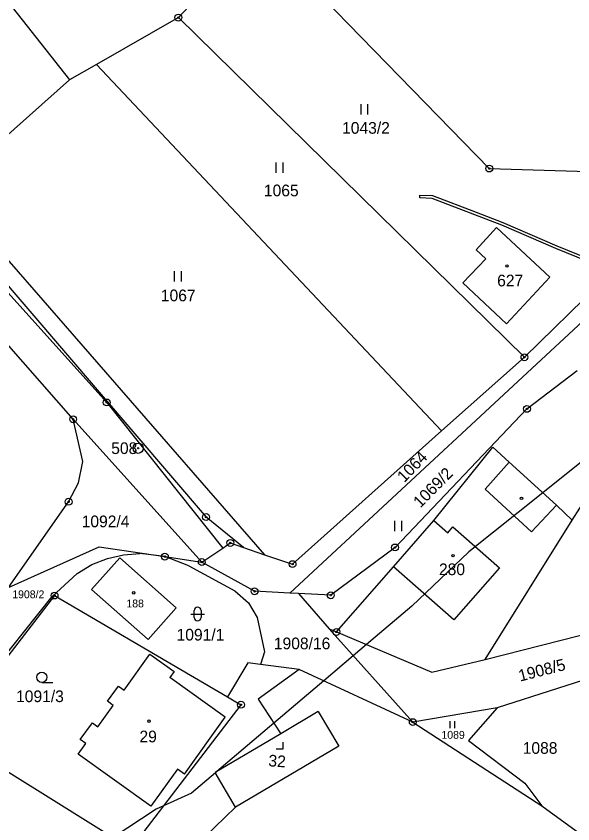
# Model space of a CAD drawing. Extents: x -445050 to -440454, y -1134563 to -1129741.
# Drawn here: x -440973 to -440892, y -1131697.7 to -1131580.2 of the extents above; entities that cross this region are included whole.
import ezdxf

# ---------------------------------------------------------------- set-up
doc = ezdxf.new("R2010")
doc.units = 0
for name, color, linetype in [('Vrstva 1', 7, 'Continuous'), ('Vrstva 16', 7, 'Continuous'), ('Vrstva 17', 7, 'Continuous'), ('Vrstva 18', 7, 'Continuous'), ('Vrstva 19', 7, 'Continuous'), ('Vrstva 24', 7, 'Continuous'), ('Vrstva 25', 7, 'Continuous'), ('Vrstva 3', 7, 'Continuous'), ('Vrstva 30', 7, 'Continuous'), ('Vrstva 37', 7, 'Continuous'), ('Vrstva 4', 7, 'Continuous'), ('Vrstva 52', 7, 'Continuous'), ('Vrstva 6', 7, 'Continuous')]:
    doc.layers.add(name, color=color, linetype=linetype)

msp = doc.modelspace()

# ---------------------------------------------------------------- linework, layer by layer
at = {"layer": 'Vrstva 1'}
for p, q in [((-440960.93, -1131657.44), (-440951.34, -1131658.85)), ((-440959.67, -1131659.1), (-440957.37, -1131658.57)), ((-440957.37, -1131658.57), (-440955.01, -1131658.4)), ((-440951.34, -1131658.85), (-440955.01, -1131658.4)), ((-440947.86, -1131660.19), (-440951.34, -1131658.85)), ((-440951.34, -1131658.85), (-440945.97, -1131659.64)), ((-440964.12, -1131661.32), (-440961.97, -1131660)), ((-440961.97, -1131660), (-440959.67, -1131659.1)), ((-440967.74, -1131664.66), (-440964.12, -1131661.32)), ((-440947.86, -1131660.19), (-440941.17, -1131663.84)), ((-440977.9, -1131677.35), (-440967.74, -1131664.66)), ((-440941.17, -1131663.84), (-440939.19, -1131665.55)), ((-440939.19, -1131665.55), (-440937.91, -1131667.71)), ((-440937.91, -1131667.71), (-440936.86, -1131672.68)), ((-440936.86, -1131672.68), (-440937.44, -1131674.52)), ((-440937.44, -1131674.52), (-440939.27, -1131674.27)), ((-440931.78, -1131675.28), (-440937.44, -1131674.52))]:
    msp.add_line(p, q, dxfattribs=at)
for points in [[(-441028.42, -1131556.07), (-440945.35, -1131653.09)], [(-440949.38, -1131580.44), (-440937.66, -1131567.98)], [(-440937.66, -1131567.98), (-440904.13, -1131602.39)], [(-440949.38, -1131580.44), (-440899.01, -1131629.84)], [(-440964.69, -1131638.87), (-441013.94, -1131582.78)], [(-440904.13, -1131602.39), (-440875.32, -1131603.26)], [(-440983.15, -1131605.46), (-440936.83, -1131658.56)], [(-440982.49, -1131611.24), (-440959.81, -1131636.42)], [(-440906.05, -1131614.2), (-440903.07, -1131610.99)], [(-440895.33, -1131618.19), (-440903.07, -1131610.99)], [(-440904.64, -1131615.52), (-440906.05, -1131614.2)], [(-440908, -1131619.04), (-440904.64, -1131615.52)], [(-440895.33, -1131618.19), (-440901.61, -1131624.99)], [(-440901.61, -1131624.99), (-440908, -1131619.04)], [(-440899.01, -1131629.84), (-440888.16, -1131619.27)], [(-440886.46, -1131620.79), (-440933.17, -1131664.15)], [(-440911.09, -1131640.57), (-440899.01, -1131629.84)], [(-440898.64, -1131637.35), (-440891.35, -1131631.79)], [(-440959.81, -1131636.42), (-440942.93, -1131657.6)], [(-440898.64, -1131637.35), (-440917.85, -1131657.51)], [(-440963.27, -1131645.03), (-440964.69, -1131638.87)], [(-440945.97, -1131659.64), (-440964.69, -1131638.87)], [(-440932.76, -1131659.94), (-440911.09, -1131640.57)], [(-440912.18, -1131653.61), (-440903.62, -1131642.93)], [(-440903.62, -1131642.93), (-440901.21, -1131645.12)], [(-440963.92, -1131648.09), (-440963.27, -1131645.03)], [(-440901.21, -1131645.12), (-440894.36, -1131651.34)], [(-440965.35, -1131650.86), (-440963.92, -1131648.09)], [(-440892.08, -1131653.56), (-440889.85, -1131650.07)], [(-440974.1, -1131663.33), (-440965.35, -1131650.86)], [(-440894.36, -1131651.34), (-440892.08, -1131653.56)], [(-440939.91, -1131657.51), (-440945.35, -1131653.09)], [(-440918.06, -1131660.32), (-440912.18, -1131653.61)], [(-440904.72, -1131673.81), (-440892.08, -1131653.56)], [(-440974.1, -1131663.33), (-440960.93, -1131657.44)], [(-440945.97, -1131659.64), (-440942.93, -1131657.6)], [(-440942.93, -1131657.6), (-440941.82, -1131656.86)], [(-440941.82, -1131656.86), (-440939.91, -1131657.51)], [(-440939.91, -1131657.51), (-440936.83, -1131658.56)], [(-440917.85, -1131657.51), (-440927.19, -1131664.47)], [(-440936.83, -1131658.56), (-440932.76, -1131659.94)], [(-440957.9, -1131659.04), (-440962.01, -1131663.64)], [(-440949.71, -1131666.28), (-440957.9, -1131659.04)], [(-440938.29, -1131663.89), (-440945.97, -1131659.64)], [(-440926.37, -1131669.8), (-440918.06, -1131660.32)], [(-440953.79, -1131670.9), (-440962.01, -1131663.64)], [(-440967.4, -1131664.5), (-440983, -1131684.66)], [(-440967.4, -1131664.5), (-440942.22, -1131679.25)], [(-440933.17, -1131664.15), (-440938.29, -1131663.89)], [(-440931.9, -1131664.22), (-440933.17, -1131664.15)], [(-440931.9, -1131664.22), (-440927.44, -1131669.35)], [(-440927.19, -1131664.47), (-440931.9, -1131664.22)], [(-440949.71, -1131666.28), (-440953.79, -1131670.9)], [(-440904.72, -1131673.81), (-440882.8, -1131668.24)], [(-440927.44, -1131669.35), (-440915.26, -1131682.92)], [(-440927.44, -1131669.35), (-440926.37, -1131669.8)], [(-440926.37, -1131669.8), (-440912.48, -1131675.65)], [(-440957.27, -1131678.27), (-440953.52, -1131673.03)], [(-440953.52, -1131673.03), (-440950, -1131675.55)], [(-440912.48, -1131675.65), (-440904.72, -1131673.81)], [(-440939.27, -1131674.27), (-440942.22, -1131679.25)], [(-440931.78, -1131675.28), (-440937.76, -1131679.59)], [(-440915.26, -1131682.92), (-440931.78, -1131675.28)], [(-440885.43, -1131675.22), (-440902.96, -1131680.85)], [(-440950, -1131675.55), (-440950.62, -1131676.41)], [(-440942.55, -1131682.18), (-440950.62, -1131676.41)], [(-440959.67, -1131679.89), (-440958.09, -1131677.68)], [(-440958.09, -1131677.68), (-440957.27, -1131678.27)], [(-440958.85, -1131680.48), (-440959.67, -1131679.89)], [(-440942.22, -1131679.25), (-440940.27, -1131680.39)], [(-440937.76, -1131679.59), (-440934.48, -1131684.6)], [(-440961.08, -1131683.59), (-440958.85, -1131680.48)], [(-440940.27, -1131680.39), (-440956.28, -1131701.3)], [(-440902.96, -1131680.85), (-440915.26, -1131682.92)], [(-440902.96, -1131680.85), (-440907.14, -1131685.6)], [(-440948.5, -1131690.49), (-440942.55, -1131682.18)], [(-440929.01, -1131681.38), (-440934.48, -1131684.6)], [(-440929.01, -1131681.38), (-440926.04, -1131686.41)], [(-440963.66, -1131685.46), (-440961.9, -1131683)], [(-440961.9, -1131683), (-440961.08, -1131683.59)], [(-440915.26, -1131682.92), (-440896.48, -1131695.1)], [(-440983, -1131684.66), (-440958.64, -1131699.84)], [(-440934.48, -1131684.6), (-440944.02, -1131690.24)], [(-440962.84, -1131686.04), (-440963.66, -1131685.46)], [(-440907.14, -1131685.6), (-440898.95, -1131691.78)], [(-440963.95, -1131687.6), (-440962.84, -1131686.04)], [(-440926.04, -1131686.41), (-440941.05, -1131695.27)], [(-440953.39, -1131695.16), (-440963.95, -1131687.6)], [(-440949.52, -1131689.76), (-440953.39, -1131695.16)], [(-440948.5, -1131690.49), (-440949.52, -1131689.76)], [(-440941.05, -1131695.27), (-440944.02, -1131690.24)], [(-440898.95, -1131691.78), (-440896.48, -1131695.1)], [(-440945.57, -1131699.63), (-440941.05, -1131695.27)], [(-440896.48, -1131695.1), (-440884.56, -1131703.79)]]:
    msp.add_lwpolyline(points, dxfattribs=at)
at = {"layer": 'Vrstva 24'}
for centre, radius in [((-440949.38, -1131580.44), 0.5), ((-440949.38, -1131580.44), 0.1), ((-440904.13, -1131602.39), 0.5), ((-440904.13, -1131602.39), 0.1), ((-440899.01, -1131629.84), 0.5), ((-440899.01, -1131629.84), 0.1), ((-440959.81, -1131636.42), 0.5), ((-440959.81, -1131636.42), 0.1), ((-440898.64, -1131637.35), 0.5), ((-440898.64, -1131637.35), 0.1), ((-440964.69, -1131638.87), 0.5), ((-440964.69, -1131638.87), 0.1), ((-440955.23, -1131643.07), 0.75), ((-440955.23, -1131643.07), 0.1), ((-440965.35, -1131650.86), 0.5), ((-440965.35, -1131650.86), 0.1), ((-440945.35, -1131653.09), 0.5), ((-440945.35, -1131653.09), 0.1), ((-440941.82, -1131656.86), 0.5), ((-440941.82, -1131656.86), 0.1), ((-440917.85, -1131657.51), 0.5), ((-440917.85, -1131657.51), 0.1), ((-440951.34, -1131658.85), 0.5), ((-440951.34, -1131658.85), 0.1), ((-440945.97, -1131659.64), 0.5), ((-440945.97, -1131659.64), 0.1), ((-440932.76, -1131659.94), 0.5), ((-440932.76, -1131659.94), 0.1), ((-440938.29, -1131663.89), 0.5), ((-440967.4, -1131664.5), 0.5), ((-440967.4, -1131664.5), 0.1), ((-440938.29, -1131663.89), 0.1), ((-440927.19, -1131664.47), 0.5), ((-440927.19, -1131664.47), 0.1), ((-440926.37, -1131669.8), 0.5), ((-440926.37, -1131669.8), 0.1), ((-440940.27, -1131680.39), 0.5), ((-440940.27, -1131680.39), 0.1), ((-440915.26, -1131682.92), 0.5), ((-440915.26, -1131682.92), 0.1)]:
    msp.add_circle(centre, radius, dxfattribs=at)
at = {"layer": 'Vrstva 25'}
for p, q in [((-440922.78, -1131594.55), (-440922.78, -1131593.05)), ((-440921.78, -1131594.55), (-440921.78, -1131593.05)), ((-440935.14, -1131603), (-440935.14, -1131601.5)), ((-440934.14, -1131603), (-440934.14, -1131601.5)), ((-440949.94, -1131618.81), (-440949.94, -1131617.31)), ((-440948.94, -1131618.81), (-440948.94, -1131617.31)), ((-440917.87, -1131655.13), (-440917.87, -1131653.63)), ((-440916.87, -1131655.13), (-440916.87, -1131653.63)), ((-440947.58, -1131667.19), (-440945.58, -1131667.19)), ((-440947.08, -1131667.69), (-440947.08, -1131666.69)), ((-440946.08, -1131666.69), (-440946.08, -1131667.69)), ((-440969.25, -1131677.15), (-440967.65, -1131677.15)), ((-440909.82, -1131683.79), (-440909.82, -1131682.78)), ((-440909.15, -1131683.79), (-440909.15, -1131682.78))]:
    msp.add_line(p, q, dxfattribs=at)
msp.add_lwpolyline([(-440935.14, -1131686.81), (-440934.14, -1131686.81), (-440934.14, -1131685.81)], dxfattribs=at)
for centre, radius in [((-440901.56, -1131616.55), 0.175), ((-440899.44, -1131650.35), 0.175), ((-440909.4, -1131658.72), 0.175), ((-440955.88, -1131664.11), 0.175), ((-440969.25, -1131676.4), 0.75), ((-440953.64, -1131682.78), 0.175)]:
    msp.add_circle(centre, radius, dxfattribs=at)
for centre, start, end in [((-440946.58, -1131666.69), 0, 180), ((-440946.58, -1131667.69), 180, 0)]:
    msp.add_arc(centre, 0.5, start, end, dxfattribs=at)
at = {"layer": 'Vrstva 3'}
for points in [[(-440906.05, -1131614.2), (-440903.07, -1131610.99)], [(-440895.33, -1131618.19), (-440903.07, -1131610.99)], [(-440904.64, -1131615.52), (-440906.05, -1131614.2)], [(-440908, -1131619.04), (-440904.64, -1131615.52)], [(-440895.33, -1131618.19), (-440901.61, -1131624.99)], [(-440901.61, -1131624.99), (-440908, -1131619.04)], [(-440918.06, -1131660.32), (-440912.18, -1131653.61)], [(-440912.18, -1131653.61), (-440910.18, -1131655.37)], [(-440910.18, -1131655.37), (-440909.44, -1131654.5)], [(-440909.44, -1131654.5), (-440902.64, -1131660.47)], [(-440957.9, -1131659.04), (-440962.01, -1131663.64)], [(-440949.71, -1131666.28), (-440957.9, -1131659.04)], [(-440909.31, -1131668.05), (-440918.06, -1131660.32)], [(-440902.64, -1131660.47), (-440909.31, -1131668.05)], [(-440953.79, -1131670.9), (-440962.01, -1131663.64)], [(-440949.71, -1131666.28), (-440953.79, -1131670.9)], [(-440957.27, -1131678.27), (-440953.52, -1131673.03)], [(-440953.52, -1131673.03), (-440950, -1131675.55)], [(-440950, -1131675.55), (-440950.62, -1131676.41)], [(-440942.55, -1131682.18), (-440950.62, -1131676.41)], [(-440959.67, -1131679.89), (-440958.09, -1131677.68)], [(-440958.09, -1131677.68), (-440957.27, -1131678.27)], [(-440958.85, -1131680.48), (-440959.67, -1131679.89)], [(-440961.08, -1131683.59), (-440958.85, -1131680.48)], [(-440948.5, -1131690.49), (-440942.55, -1131682.18)], [(-440963.66, -1131685.46), (-440961.9, -1131683)], [(-440961.9, -1131683), (-440961.08, -1131683.59)], [(-440962.84, -1131686.04), (-440963.66, -1131685.46)], [(-440963.95, -1131687.6), (-440962.84, -1131686.04)], [(-440953.39, -1131695.16), (-440963.95, -1131687.6)], [(-440949.52, -1131689.76), (-440953.39, -1131695.16)], [(-440948.5, -1131690.49), (-440949.52, -1131689.76)]]:
    msp.add_lwpolyline(points, dxfattribs=at)
at = {"layer": 'Vrstva 30'}
msp.add_lwpolyline([(-440886.69, -1131617.16), (-440894.46, -1131614), (-440902.3, -1131610.61), (-440912.46, -1131606.73), (-440914.26, -1131606.65), (-440914.24, -1131606.25), (-440912.38, -1131606.33), (-440906.03, -1131608.76), (-440902.16, -1131610.24), (-440894.3, -1131613.64), (-440886.54, -1131616.79), (-440886.69, -1131617.16)], dxfattribs=at)
at = {"layer": 'Vrstva 37'}
for centre in [(-440901.56, -1131616.55), (-440909.4, -1131658.72), (-440955.88, -1131664.11), (-440953.64, -1131682.78)]:
    msp.add_circle(centre, 0.175, dxfattribs=at)
at = {"layer": 'Vrstva 4'}
for points in [[(-440904.74, -1131649.03), (-440901.21, -1131645.12)], [(-440897.99, -1131655.25), (-440904.74, -1131649.03)], [(-440894.36, -1131651.34), (-440897.99, -1131655.25)], [(-440912.18, -1131653.61), (-440910.18, -1131655.37)], [(-440910.18, -1131655.37), (-440909.44, -1131654.5)], [(-440909.44, -1131654.5), (-440902.64, -1131660.47)], [(-440909.31, -1131668.05), (-440918.06, -1131660.32)], [(-440902.64, -1131660.47), (-440909.31, -1131668.05)]]:
    msp.add_lwpolyline(points, dxfattribs=at)
at = {"layer": 'Vrstva 52'}
msp.add_lwpolyline([(-440879.45, -1131636.05), (-440896.33, -1131649.55), (-440907.09, -1131658.16), (-440915.38, -1131666.03), (-440922, -1131671.64), (-440923.92, -1131673.27), (-440928.23, -1131676.92), (-440935.48, -1131683.07), (-440943.77, -1131690.09), (-440943.99, -1131690.28), (-440947.48, -1131693.24), (-440951.53, -1131695.09), (-440952.59, -1131695.58), (-440958.86, -1131699.7)], dxfattribs=at)
at = {"layer": 'Vrstva 6'}
for points in [[(-440983.23, -1131566.7), (-440965.2, -1131589.5)], [(-440949.38, -1131580.44), (-440961.3, -1131587.27)], [(-440961.3, -1131587.27), (-440965.2, -1131589.5)], [(-440911.09, -1131640.57), (-440961.3, -1131587.27)], [(-440965.2, -1131589.5), (-440983.15, -1131605.46)]]:
    msp.add_lwpolyline(points, dxfattribs=at)

# ---------------------------------------------------------------- texts
at = {"layer": 'Vrstva 16'}
msp.add_text('1908/2', height=1.14, dxfattribs=at).set_placement((-440973.55, -1131664.9))
at = {"layer": 'Vrstva 17'}
msp.add_text('508', height=1.7, dxfattribs=at).set_placement((-440959.15, -1131643.92))
at = {"layer": 'Vrstva 18'}
for s, height, p in [('1043/2', 1.7, (-440925.55, -1131597.33)), ('1065', 1.7, (-440936.93, -1131606.43)), ('1067', 1.7, (-440951.93, -1131621.7)), ('1092/4', 1.7, (-440963.45, -1131654.57)), ('1091/1', 1.7, (-440949.64, -1131671.05)), ('1908/16', 1.7, (-440935.48, -1131672.32)), ('1091/3', 1.7, (-440973, -1131680.01)), ('1089', 1.14, (-440911.09, -1131685.34)), ('1088', 1.7, (-440899.26, -1131687.53))]:
    msp.add_text(s, height=height, dxfattribs=at).set_placement(p)
for s, rotation, p in [('1064', 46.0107, (-440916.5, -1131648.16)), ('1069/2', 45.4707, (-440914.17, -1131651.86)), ('1908/5', 14.4054, (-440899.64, -1131677.03))]:
    msp.add_text(s, height=1.7, rotation=rotation, dxfattribs=at).set_placement(p)
at = {"layer": 'Vrstva 19'}
for s, height, p in [('627', 1.7, (-440902.98, -1131619.53)), ('280', 1.7, (-440911.45, -1131661.54)), ('188', 1.14, (-440956.94, -1131666.23)), ('29', 1.7, (-440955.04, -1131685.86))]:
    msp.add_text(s, height=height, dxfattribs=at).set_placement(p)
msp.add_text('32', height=1.7, rotation=356.1061, dxfattribs=at).set_placement((-440936.32, -1131689.34))

doc.saveas('drawing.dxf')
